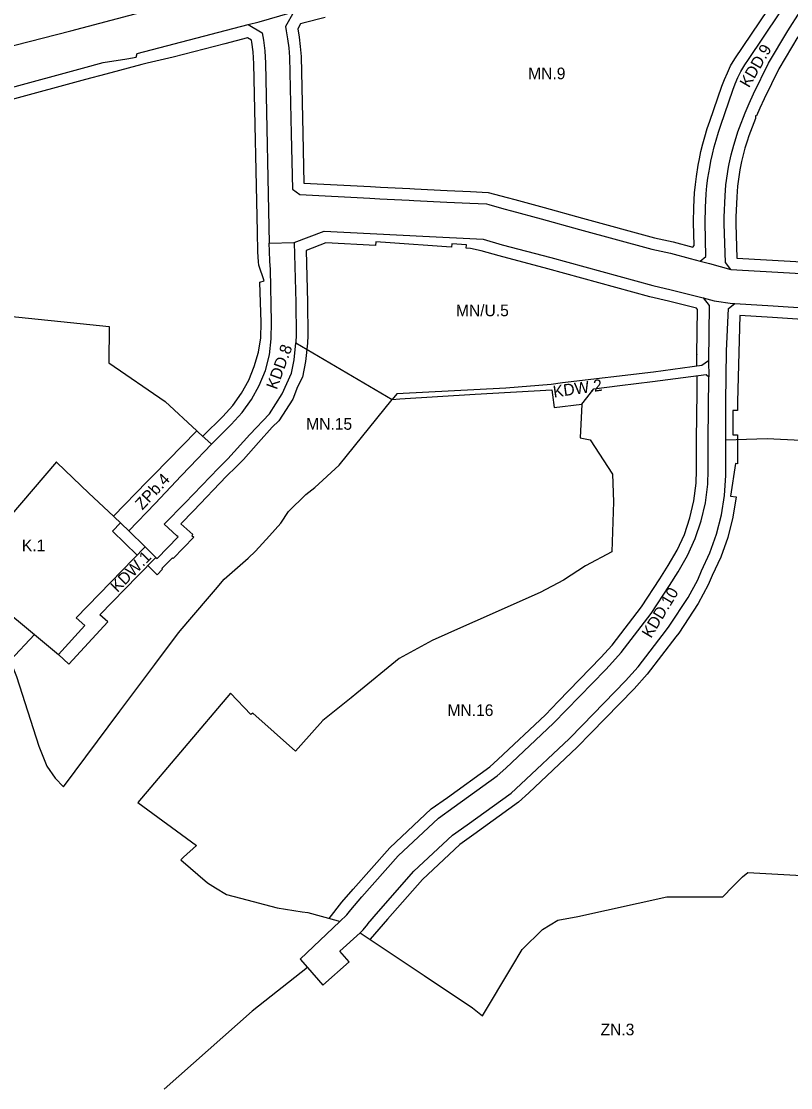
# Model space of a CAD drawing. Extents: x 7414808 to 7417449, y 5544732 to 5546764.
# Drawn here: x 7415189.8 to 7415519.6, y 5545373 to 5545829.9 of the extents above; entities that cross this region are included whole.
import ezdxf

# ---------------------------------------------------------------- set-up
doc = ezdxf.new("R2010")
doc.units = 0
for name, color, linetype in [('LIN_Linie Rozgraniczajace', 7, 'Continuous'), ('LIN_nieprzekraczale linie zabudowy', 7, 'Continuous'), ('TXT_Oznaczenia Przeznaczenia', 7, 'Continuous')]:
    doc.layers.add(name, color=color, linetype=linetype)

msp = doc.modelspace()

# ---------------------------------------------------------------- linework, layer by layer
at = {"layer": 'LIN_Linie Rozgraniczajace'}
for p, q in [((7415296.05, 5545734.83), (7415306.74, 5545735.05)), ((7415307.4, 5545692.07), (7415348.73, 5545667.79)), ((7415484.32, 5545684.4), (7415484.48, 5545677.54)), ((7415235.93, 5545611.55), (7415242.91, 5545604.7)), ((7415242.91, 5545604.7), (7415247.5, 5545600.2)), ((7415326.34, 5545444.23), (7415309.29, 5545427.98))]:
    msp.add_line(p, q, dxfattribs=at)
for points in [[(7415480.78, 5545727.12), (7415483.24, 5545729.05), (7415482.96, 5545743.71), (7415483.01, 5545750.02), (7415483.36, 5545755.98), (7415483.69, 5545759.38), (7415484.11, 5545762.65), (7415484.85, 5545767.3), (7415485.36, 5545769.95), (7415486, 5545772.89), (7415486.78, 5545776.08), (7415487.58, 5545779), (7415488.59, 5545782.35), (7415489.61, 5545785.4), (7415494.82, 5545800.38), (7415495.83, 5545803.08), (7415496.97, 5545805.76), (7415498.25, 5545808.39), (7415499.87, 5545811.19), (7415501.45, 5545813.54), (7415521.39, 5545843.2), (7415523.29, 5545847.45), (7415524.15, 5545851.33), (7415524.45, 5545855.9)], [(7415493.88, 5545723.56), (7415491.6, 5545726.46), (7415491.04, 5545743.03), (7415491.05, 5545746.02), (7415491.44, 5545755.02), (7415491.83, 5545759.76), (7415492.93, 5545767.37), (7415493.22, 5545768.86), (7415494.06, 5545772.67), (7415495.16, 5545776.83), (7415496.15, 5545780.07), (7415496.98, 5545782.52), (7415497.64, 5545784.32), (7415500.03, 5545790.71), (7415501.74, 5545794.67), (7415503.69, 5545798.77), (7415510.12, 5545811.91), (7415518.31, 5545825.81), (7415523.57, 5545834.09), (7415530.15, 5545844.72), (7415536.38, 5545855.13)], [(7414998.29, 5545778.83), (7415029.23, 5545783.64), (7415077.77, 5545791.68), (7415111.05, 5545799.42), (7415162.88, 5545813.44), (7415210.97, 5545825.8), (7415265.57, 5545840.42), (7415307.77, 5545850.49)], [(7415287.07, 5545828.44), (7415291.72, 5545829.65), (7415305.05, 5545833.54), (7415306.62, 5545833.93)], [(7415306.62, 5545833.93), (7415303, 5545827.57), (7415303.34, 5545825.82), (7415303.91, 5545822.39), (7415304.38, 5545818.53), (7415304.67, 5545814.54), (7415305.43, 5545781.66), (7415305.99, 5545757.95), (7415309.2, 5545755.61), (7415339.17, 5545754.09), (7415343.46, 5545753.86), (7415356.05, 5545753.18), (7415358.04, 5545753.07), (7415372.13, 5545752.4), (7415382.09, 5545751.91), (7415389.12, 5545751.61), (7415390.12, 5545751.34), (7415396.66, 5545749.55), (7415399.95, 5545748.65), (7415412.64, 5545745.2), (7415429.07, 5545740.63), (7415460.05, 5545732.26), (7415468.08, 5545730.46), (7415476.48, 5545728.28), (7415480.78, 5545727.12)], [(7415076.55, 5545773.66), (7415124.61, 5545785.87), (7415153.38, 5545793.44), (7415163.14, 5545796.01), (7415175.24, 5545798.83), (7415178.09, 5545799.48), (7415184.02, 5545801.09), (7415216.01, 5545809.79), (7415224.92, 5545812.16), (7415234.97, 5545813.75), (7415239.08, 5545814.55), (7415239.39, 5545816.05), (7415287.07, 5545828.44)], [(7415287.07, 5545828.44), (7415293.03, 5545824.93), (7415293.59, 5545821.74), (7415294.16, 5545817.2), (7415294.47, 5545811.86), (7415296.05, 5545734.83)], [(7415014.81, 5545755.19), (7415017.48, 5545728.34), (7415018.77, 5545715.37), (7415036.99, 5545717.06), (7415031.47, 5545691.02), (7415049.17, 5545682.26), (7415060.5, 5545676.64), (7415091.25, 5545669.34), (7415103.65, 5545666.39), (7415124.44, 5545662.89), (7415124.9, 5545669.82), (7415125.43, 5545684.36), (7415125.59, 5545693.03), (7415129.16, 5545706.49), (7415129.15, 5545709.3), (7415227.47, 5545699.08), (7415227.26, 5545683.57), (7415251.41, 5545666.98), (7415264.96, 5545654.43)], [(7415306.74, 5545735.05), (7415319.56, 5545740.01), (7415361.9, 5545737.79), (7415387.77, 5545736.47), (7415395.9, 5545734.15), (7415416.71, 5545728.7), (7415460.45, 5545716.61), (7415468.32, 5545714.75), (7415480.87, 5545711.65), (7415482.13, 5545711.34)], [(7415271.27, 5545648.71), (7415279.75, 5545657.06), (7415284.4, 5545662.19), (7415288.42, 5545667.83), (7415291.77, 5545673.89), (7415294.4, 5545680.3), (7415296.21, 5545686.97), (7415296.94, 5545693.79), (7415297.05, 5545701.03), (7415296.59, 5545723.51), (7415296.37, 5545727.13), (7415296.12, 5545731.37), (7415296.05, 5545734.83)], [(7415306.74, 5545735.05), (7415307.39, 5545709.46), (7415307.63, 5545695.44), (7415307.43, 5545692.36), (7415307.4, 5545692.07)], [(7415480.78, 5545727.12), (7415484.8, 5545726.03), (7415493.88, 5545723.56)], [(7415493.88, 5545723.56), (7415519.01, 5545722.12), (7415526.34, 5545721.71), (7415537.82, 5545721.02), (7415545.75, 5545720.55), (7415567.96, 5545718.09), (7415577.98, 5545716.99), (7415582.85, 5545715.92), (7415595.35, 5545713.4), (7415607.29, 5545711.07), (7415618.11, 5545708.93), (7415629.85, 5545706.62), (7415638.79, 5545704.93)], [(7415482.13, 5545711.34), (7415484.61, 5545708.15), (7415484.32, 5545684.4)], [(7415482.13, 5545711.34), (7415486.84, 5545710.17), (7415494.65, 5545709.03), (7415495.61, 5545708.97)], [(7415491.71, 5545650.6), (7415491.78, 5545666.82), (7415492.03, 5545688.72), (7415492.99, 5545706.75), (7415495.61, 5545708.97)], [(7415495.61, 5545708.97), (7415512.11, 5545707.9), (7415544.5, 5545705.8), (7415576.18, 5545701.95), (7415590.24, 5545699.42), (7415599.66, 5545697.46), (7415607.83, 5545695.76), (7415625.63, 5545692.21), (7415635.08, 5545690.22)], [(7415247.5, 5545600.2), (7415247.94, 5545599.77), (7415256.97, 5545608.98), (7415256.51, 5545609.4), (7415251.04, 5545614.41), (7415259.95, 5545623.56), (7415274.24, 5545638.43), (7415278.31, 5545642.44), (7415287.76, 5545652.77), (7415296.17, 5545661.76), (7415301.65, 5545670.3), (7415305.55, 5545679.07), (7415306.71, 5545684.79), (7415307.4, 5545692.07)], [(7415484.32, 5545684.4), (7415481.55, 5545682.41), (7415469, 5545680.69), (7415460.81, 5545679.59), (7415421.81, 5545674.94), (7415416.89, 5545674.28)], [(7415326.34, 5545444.23), (7415329.31, 5545447.06), (7415331.03, 5545449.22), (7415335.79, 5545454.72), (7415351.27, 5545472.32), (7415368.55, 5545488.51), (7415375.37, 5545493.28), (7415393.8, 5545506.61), (7415397.47, 5545509.94), (7415417.94, 5545529.17), (7415423.53, 5545534.93), (7415440.18, 5545552.05), (7415441.85, 5545553.81), (7415446.89, 5545559.38), (7415459.72, 5545576.16), (7415467.62, 5545588.21), (7415471.38, 5545594.02), (7415475.39, 5545600.94), (7415478.68, 5545608.23), (7415481.23, 5545615.81), (7415483.01, 5545623.61), (7415484, 5545631.54), (7415484.22, 5545637.51), (7415484.21, 5545650.61), (7415484.48, 5545677.54)], [(7415416.89, 5545674.28), (7415397.52, 5545672.71), (7415350.68, 5545670.22), (7415348.73, 5545667.79)], [(7415430.11, 5545665.86), (7415432.15, 5545668.49), (7415435.23, 5545672.44), (7415446.35, 5545673.83), (7415460.4, 5545675.58), (7415483.35, 5545678.56), (7415484.48, 5545677.54)], [(7415348.73, 5545667.79), (7415352.04, 5545668.18), (7415384.3, 5545670.09), (7415417.19, 5545672.04)], [(7415417.19, 5545672.04), (7415417.48, 5545669.82), (7415418.18, 5545664.36), (7415430.11, 5545665.86)], [(7415195.41, 5545567.15), (7415185, 5545555.96), (7415187.67, 5545549.14), (7415197.25, 5545519.26), (7415200.72, 5545510.73), (7415204.22, 5545505.53), (7415207.83, 5545501.85), (7415232.02, 5545534.26), (7415246.98, 5545554.27), (7415257.15, 5545567.91), (7415261.16, 5545572.61), (7415272.98, 5545586.38), (7415276.77, 5545590.85), (7415287.06, 5545599.91), (7415290.13, 5545602.87), (7415293.17, 5545606.19), (7415296.17, 5545609.45), (7415301.08, 5545614.81), (7415304.27, 5545619.8), (7415311.8, 5545627.19), (7415315.56, 5545630.13), (7415326.03, 5545639.72), (7415348.73, 5545667.79)], [(7415430.11, 5545665.86), (7415429.4, 5545651.34), (7415433.68, 5545650.61), (7415443.21, 5545635.89), (7415443.69, 5545624.02), (7415442.93, 5545602.57), (7415431.69, 5545596.59), (7415422.24, 5545590.4), (7415412.12, 5545585.16), (7415384.22, 5545572.76), (7415379.34, 5545570.59), (7415365.9, 5545564.61), (7415351.71, 5545556.82), (7415333.63, 5545542.04), (7415331.18, 5545540.03), (7415328.97, 5545538.27), (7415318.96, 5545530.3), (7415309.53, 5545519.73), (7415307.29, 5545517.22), (7415289.02, 5545533.47), (7415288.16, 5545532.88), (7415279.5, 5545541.94), (7415239.78, 5545495.23), (7415264.8, 5545476.78), (7415259.28, 5545471.79), (7415258.18, 5545470.66), (7415269.59, 5545460.74), (7415273.06, 5545458.63), (7415277.72, 5545455.8), (7415283.73, 5545454.21), (7415299.48, 5545450.07), (7415310.21, 5545448.37), (7415312.6, 5545447.99), (7415325.57, 5545444.48), (7415326.34, 5545444.23)], [(7415229.23, 5545617.82), (7415243.7, 5545632.65), (7415246.41, 5545635.43), (7415264.96, 5545654.43)], [(7415264.96, 5545654.43), (7415265.2, 5545654.2), (7415265.73, 5545653.72), (7415271.27, 5545648.71)], [(7415235.93, 5545611.55), (7415247.15, 5545623.33), (7415258.36, 5545635.12), (7415261.99, 5545638.95), (7415271.27, 5545648.71)], [(7415335.11, 5545439.46), (7415336.34, 5545440.64), (7415338.27, 5545443.06), (7415338.34, 5545443.15), (7415342.95, 5545448.47), (7415358.1, 5545465.7), (7415374.56, 5545481.12), (7415380.88, 5545485.54), (7415399.79, 5545499.22), (7415403.91, 5545502.96), (7415424.61, 5545522.4), (7415430.35, 5545528.31), (7415448.78, 5545547.31), (7415454.2, 5545553.29), (7415466.34, 5545569.17), (7415467.48, 5545570.67), (7415475.58, 5545583.03), (7415479.73, 5545590.6), (7415481.36, 5545594.46), (7415484.95, 5545602.14), (7415487.8, 5545610.13), (7415489.89, 5545618.35), (7415491.2, 5545626.74), (7415491.71, 5545635.2), (7415491.72, 5545636.42), (7415491.71, 5545650.6)], [(7415491.71, 5545650.6), (7415509.49, 5545651.06), (7415523.88, 5545650.45), (7415533.32, 5545649.87), (7415536.34, 5545649.36), (7415555.51, 5545647.21), (7415560.5, 5545646.8), (7415570.82, 5545645.14)], [(7415229.23, 5545617.82), (7415218.68, 5545627.77), (7415204.94, 5545640.79), (7415204.93, 5545641.18), (7415163.9, 5545593.3), (7415195.41, 5545567.15)], [(7415229.23, 5545617.82), (7415229.37, 5545617.69), (7415235.93, 5545611.55)], [(7415205.76, 5545558.56), (7415217.07, 5545571.06), (7415213.28, 5545574.22), (7415242.91, 5545604.7)], [(7415205.76, 5545558.56), (7415210.17, 5545554.49), (7415226.81, 5545572.53), (7415223.4, 5545575.61), (7415239.72, 5545592.26), (7415247.5, 5545600.2)], [(7415195.41, 5545567.15), (7415205.76, 5545558.56)], [(7415490.55, 5545454.78), (7415494.8, 5545459.23), (7415498.58, 5545462.97), (7415498.95, 5545463.34), (7415501.15, 5545465.22), (7415521.79, 5545464.09), (7415527.71, 5545463.61), (7415537.63, 5545470.61), (7415545.57, 5545476.39), (7415551.63, 5545479.42), (7415560, 5545481.81), (7415584.84, 5545488.37), (7415575.63, 5545437.61), (7415570.97, 5545406.83)], [(7415335.03, 5545439.39), (7415362.4, 5545421.08), (7415383.22, 5545407.15), (7415387.44, 5545403.82), (7415399.98, 5545424.72), (7415404.42, 5545432.12), (7415413.14, 5545440.8), (7415419.7, 5545444.78), (7415428.31, 5545446.29), (7415466.42, 5545454.8), (7415490.55, 5545454.78)], [(7415309.29, 5545427.98), (7415312.43, 5545424.43), (7415319.05, 5545416.94), (7415330.29, 5545426.87), (7415326.29, 5545431.4), (7415335.03, 5545439.39), (7415335.11, 5545439.46)], [(7415312.43, 5545424.43), (7415288.68, 5545405.72), (7415251.03, 5545372.38)]]:
    msp.add_lwpolyline(points, dxfattribs=at)
at = {"layer": 'LIN_nieprzekraczale linie zabudowy'}
for p, q in [((7415228.91, 5545611.43), (7415232.28, 5545614.97)), ((7415239.43, 5545601.12), (7415228.91, 5545611.43))]:
    msp.add_line(p, q, dxfattribs=at)
for points in [[(7415310.45, 5545829.1), (7415309.45, 5545828.81), (7415308.26, 5545826.71), (7415308.86, 5545823.1), (7415309.35, 5545819.01), (7415309.67, 5545814.78), (7415310.43, 5545781.77), (7415310.93, 5545760.53), (7415339.43, 5545759.08), (7415343.73, 5545758.85), (7415356.32, 5545758.17), (7415358.3, 5545758.06), (7415372.37, 5545757.39), (7415382.32, 5545756.9), (7415389.9, 5545756.58), (7415397.98, 5545754.37), (7415401.27, 5545753.47), (7415413.97, 5545750.02), (7415430.39, 5545745.45), (7415461.25, 5545737.12), (7415469.26, 5545735.32), (7415477.65, 5545733.14), (7415478.15, 5545733.83), (7415477.96, 5545743.68), (7415478.01, 5545750.19), (7415478.37, 5545756.37), (7415478.72, 5545759.94), (7415479.16, 5545763.36), (7415479.93, 5545768.17), (7415480.46, 5545770.95), (7415481.13, 5545774.02), (7415481.94, 5545777.34), (7415482.77, 5545780.38), (7415483.83, 5545783.87), (7415484.87, 5545787.01), (7415490.12, 5545802.08), (7415491.19, 5545804.94), (7415492.42, 5545807.84), (7415493.84, 5545810.74), (7415495.63, 5545813.84), (7415517, 5545845.63)], [(7415319.99, 5545831.43), (7415310.45, 5545829.1)], [(7415267.56, 5545652.06), (7415267.7, 5545652.22), (7415276.14, 5545660.52), (7415280.5, 5545665.33), (7415284.18, 5545670.5), (7415287.25, 5545676.05), (7415289.66, 5545681.93), (7415291.38, 5545688.04), (7415292.38, 5545694.3), (7415292.65, 5545700.78), (7415292.65, 5545700.88), (7415292.01, 5545718.11), (7415293.91, 5545718.73), (7415291.65, 5545725.35), (7415291.38, 5545726.83), (7415291.13, 5545731.16), (7415290.95, 5545739.73), (7415289.47, 5545811.67), (7415289.18, 5545816.75), (7415288.65, 5545820.99), (7415288.51, 5545821.79), (7415286.78, 5545822.81), (7415276.96, 5545820.28), (7415254.84, 5545814.53), (7415243.66, 5545811.99), (7415241.47, 5545811.37), (7415225.96, 5545807.26), (7415217.31, 5545804.96), (7415185.33, 5545796.26)], [(7415522.58, 5545823.2), (7415514.53, 5545809.54), (7415508.19, 5545796.6), (7415506.3, 5545792.6), (7415504.91, 5545789.39), (7415504.56, 5545789.43), (7415504.43, 5545788.19), (7415502.33, 5545782.59), (7415501.7, 5545780.86), (7415500.91, 5545778.53), (7415499.97, 5545775.46), (7415498.92, 5545771.49), (7415498.56, 5545769.87), (7415497.82, 5545766.3), (7415496.8, 5545759.19), (7415496.43, 5545754.7), (7415496.05, 5545745.91), (7415496.04, 5545743.11), (7415496.54, 5545728.42), (7415519.29, 5545727.11), (7415526.63, 5545726.7)], [(7415479.29, 5545682.1), (7415479.35, 5545687.23), (7415479.35, 5545687.16), (7415479.59, 5545706.46), (7415479.24, 5545706.9), (7415467.15, 5545709.89), (7415459.21, 5545711.77), (7415415.41, 5545723.87), (7415394.58, 5545729.33), (7415386.95, 5545731.51), (7415382.32, 5545732.49), (7415380.41, 5545732.62), (7415380.54, 5545734.07), (7415374.34, 5545734.52), (7415374.24, 5545733.07), (7415372.09, 5545733.2), (7415347.86, 5545734.89), (7415341.69, 5545735.31), (7415341.58, 5545733.86), (7415320.37, 5545734.96), (7415311.83, 5545731.66), (7415312.39, 5545709.58), (7415312.64, 5545695.32), (7415312.42, 5545691.96), (7415311.66, 5545684.05), (7415310.3, 5545677.36), (7415308.14, 5545673.32), (7415306.14, 5545668.04), (7415300.13, 5545658.68), (7415297.28, 5545656.04), (7415291.43, 5545649.37), (7415285.01, 5545642.07), (7415281.91, 5545638.97), (7415277.8, 5545634.92), (7415263.55, 5545620.09), (7415258.22, 5545614.61), (7415263.29, 5545609.97), (7415262.91, 5545609.54), (7415263.78, 5545608.79), (7415254.86, 5545599.69), (7415254.86, 5545599.69), (7415254.53, 5545600.01), (7415250.02, 5545595.41), (7415250.35, 5545595.09), (7415250.35, 5545595.09), (7415248.01, 5545592.7), (7415247.57, 5545593.13), (7415244.01, 5545596.64)], [(7415544.04, 5545700.82), (7415511.79, 5545702.91), (7415497.84, 5545703.81), (7415496.77, 5545666.8), (7415496.77, 5545666.8), (7415496.76, 5545663.16), (7415494.76, 5545663.16), (7415494.72, 5545652.65), (7415496.72, 5545652.65), (7415496.71, 5545650.59), (7415496.72, 5545640.28), (7415495.96, 5545640.39), (7415493.81, 5545626.46), (7415496.16, 5545626.09), (7415494.8, 5545617.35), (7415492.59, 5545608.67), (7415489.58, 5545600.24), (7415485.93, 5545592.43), (7415484.24, 5545588.42), (7415479.87, 5545580.45), (7415471.56, 5545567.77), (7415470.31, 5545566.14), (7415458.04, 5545550.09), (7415452.43, 5545543.89), (7415433.94, 5545524.83), (7415428.11, 5545518.83), (7415407.31, 5545499.29), (7415402.95, 5545495.33), (7415383.77, 5545481.46), (7415377.71, 5545477.23), (7415361.7, 5545462.21), (7415346.72, 5545445.19), (7415339.32, 5545436.63)], [(7415321.7, 5545445.53), (7415327.18, 5545452.41), (7415332.02, 5545458.01), (7415347.68, 5545475.8), (7415365.4, 5545492.41), (7415372.47, 5545497.35), (7415390.65, 5545510.5), (7415394.08, 5545513.61), (7415414.43, 5545532.74), (7415419.94, 5545538.41), (7415438.2, 5545557.23), (7415443.04, 5545562.58), (7415455.64, 5545579.06), (7415463.43, 5545590.94), (7415467.12, 5545596.64), (7415470.93, 5545603.23), (7415474.02, 5545610.06), (7415476.41, 5545617.17), (7415478.08, 5545624.48), (7415479.01, 5545631.95), (7415479.22, 5545637.58), (7415479.21, 5545650.61), (7415479.21, 5545650.66), (7415479.42, 5545670.91), (7415479.49, 5545678.06)]]:
    msp.add_lwpolyline(points, dxfattribs=at)

# ---------------------------------------------------------------- texts
at = {"layer": 'TXT_Oznaczenia Przeznaczenia'}
for s, rotation, p in [('KDD.9', 59.8049, (7415501.7, 5545801.09)), ('KDD.8', 70, (7415299.31, 5545671.77)), ('KDW.2', 8.1525, (7415418.08, 5545668.66)), ('ZPb.4', 47, (7415241.7, 5545620.22)), ('KDW.1', 45.4254, (7415231, 5545584.86)), ('KDD.10', 59.078, (7415459.7, 5545565.26))]:
    msp.add_text(s, height=5, rotation=rotation, dxfattribs=at).set_placement(p)
for s, p in [('MN.9', (7415407.04, 5545805.03)), ('MN/U.5', (7415376.09, 5545703.51)), ('MN.15', (7415311.89, 5545654.87)), ('K.1', (7415190.02, 5545602.79)), ('MN.16', (7415372.45, 5545532.22)), ('ZN.3', (7415438.07, 5545395.41))]:
    msp.add_text(s, height=5, dxfattribs=at).set_placement(p)

doc.saveas('drawing.dxf')
